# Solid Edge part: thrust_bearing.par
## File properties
Title: Thrust bearing
Author: Abhinav Rai
Template: Normal.par
Last saved by: SOFT
Revision: 22
Application: Solid Edge
Accuracy: 0.99
Material: aluminum
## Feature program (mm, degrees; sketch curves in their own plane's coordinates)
sketch for "unnamed RevolvedProtrusion 1" plane through (0, 0, 0) normal (0, -1, 0) x-axis (1, 0, 0)
  line (47.625, 16.8036) -> (66.929, 16.8036)
  line (66.929, 16.8036) -> (73.025, 10.7076)
  line (73.025, 10.7076) -> (73.025, -12.0254)
  line (73.025, -12.0254) -> (66.929, -18.1214)
  line (66.929, -18.1214) -> (47.625, -18.1214)
  line (47.625, -18.1214) -> (47.625, -7.1994)
  line (61.5714, -7.1994) -> (47.625, -7.1994)
  line (61.5714, 5.8816) -> (61.5714, -7.1994)
  line (47.625, 5.8816) -> (61.5714, 5.8816)
  line (47.625, 5.8816) -> (47.625, 16.8036)
revolve "unnamed RevolvedProtrusion 1" add finite 360 deg
sketch for "unnamed RevolvedProtrusion 2" plane through (0, 0, 0) normal (1, 0, 0) x-axis (0, 1, 0)
  line (69.977, 13.7556) -> (73.0652, 13.7556)
  line (73.0652, 13.7556) -> (74.6125, 12.2083)
  line (74.6125, 12.2083) -> (74.6125, -13.4669)
  line (74.6125, -13.4669) -> (73.006, -15.0734)
  line (73.006, -15.0734) -> (69.977, -15.0734)
revolve "unnamed RevolvedProtrusion 2" add full turn 360 deg
sketch for "unnamed RevolvedProtrusion 3" plane through (0, 0, 0) normal (0, -1, 0) x-axis (1, 0, 0)
revolve "unnamed RevolvedProtrusion 3" add full turn 360 deg about sketch line (-54.9674, 10.1232) -> (-54.9674, -18.1214)
pattern "unnamed Pattern 1" of "unnamed RevolvedProtrusion 3"
pattern "unnamed Pattern 2"
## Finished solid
Body 1: solid body, 39 faces, 39 edges, 25 vertices.
  Faces by surface: torus 25, plane 6, cone 4, cylinder 4
  Edges by curve: circle 39
Bounding box of the edges (mm; curved faces can reach further): 149.225 x 149.225 x 34.925, from (-74.6125, -74.6125, -18.1214) to (74.6125, 74.6125, 16.8036).
Cylindrical faces by radius (mm): R47.625 x2, R61.5714 x1, R74.6125 x1
Conical faces (half-angle, radius in mm at the cone's reference point): 45 deg R66.929 x1, 45 deg R73.025 x1, 45 deg R73.0652 x1, 45 deg R74.6125 x1
Toroidal faces (ring radius, tube radius in mm): R-0.1023 r6.604 x25
Planar faces by outward normal: +z 3, -z 3
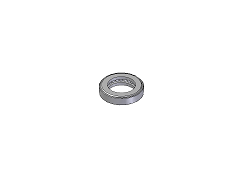
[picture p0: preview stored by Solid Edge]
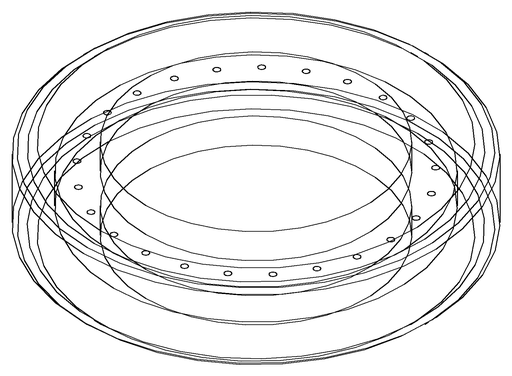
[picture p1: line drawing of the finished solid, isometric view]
